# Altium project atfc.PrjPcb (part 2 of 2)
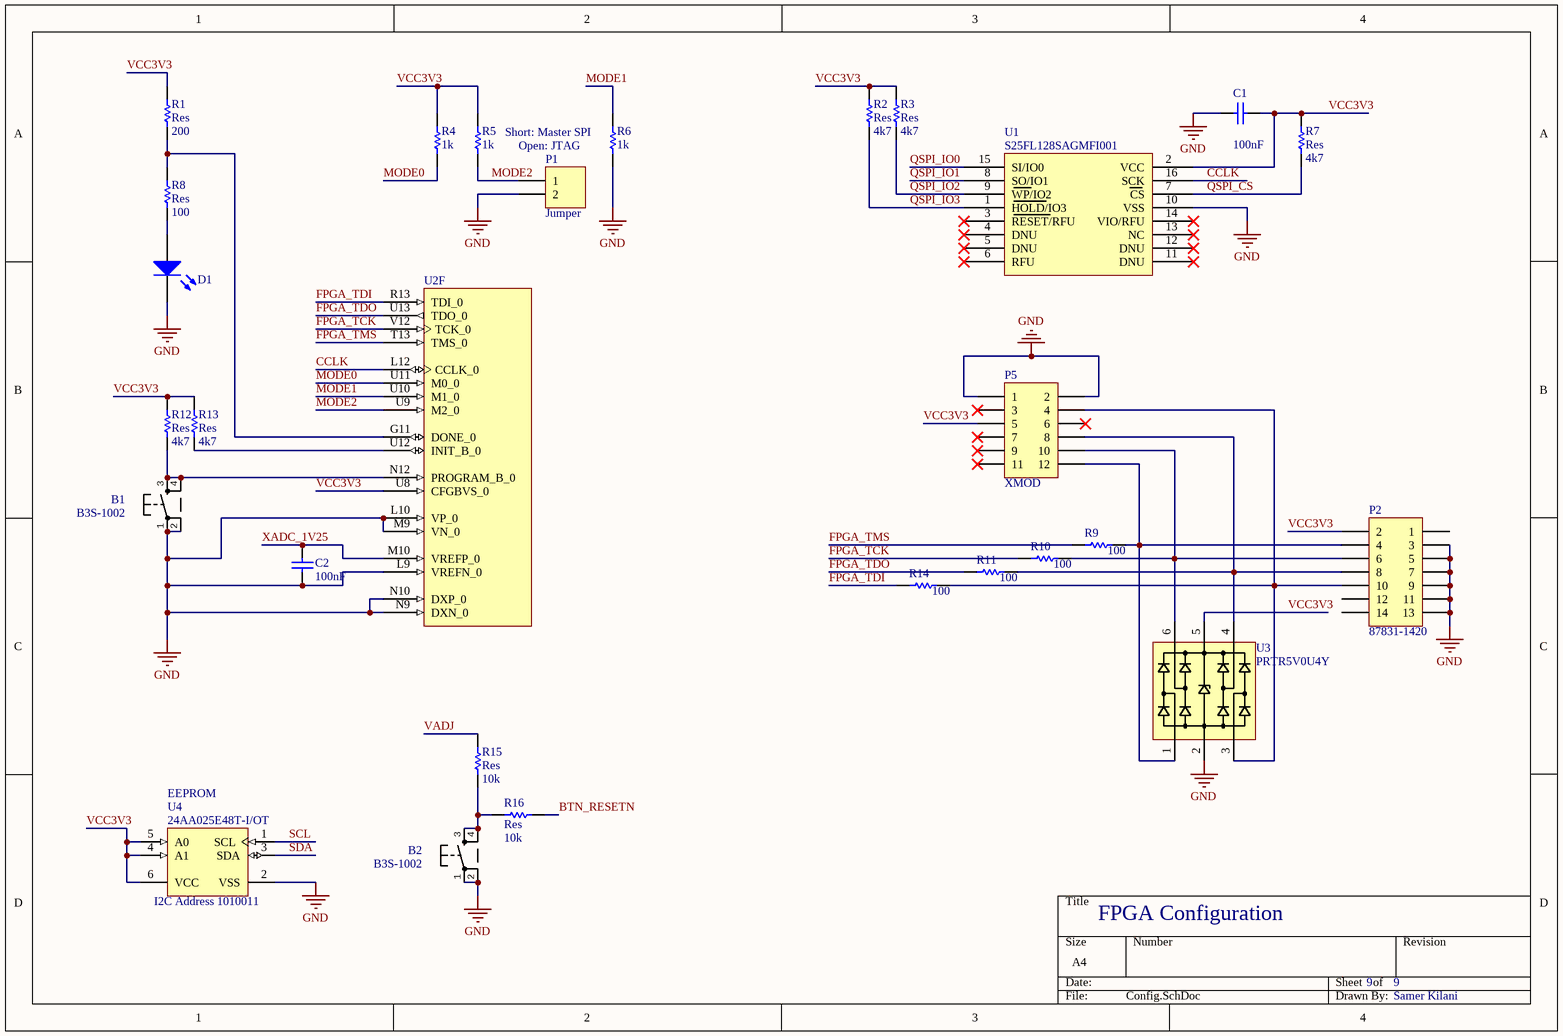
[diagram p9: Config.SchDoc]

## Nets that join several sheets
GND: PWR_APD5052 (51 pins), FPGA_PWR (144 pins), SFP (43 pins), IO (16 pins), FMC (64 pins), FPGA_Banks1 (6 pins), FPGA_Banks2 (6 pins), Regulators (39 pins), Config (25 pins)
3V3_I_MON: PWR_APD5052 (Rout2.2 U10.1), FPGA_Banks1 (U2.H14)
12V0_I_MON: PWR_APD5052 (Rout1.2 U9.1), FPGA_Banks1 (U2.H15)
BTN_RESETN: FPGA_Banks2 (U2.Y2), Config (R16.1)
DIP1: IO (R48.1 S1.1), FPGA_Banks1 (U2.AA18)
DIP2: IO (R49.1 S1.2), FPGA_Banks1 (U2.AA19)
DIP3: IO (R50.1 S1.3), FPGA_Banks1 (U2.AA20)
DIP4: IO (R51.1 S1.4), FPGA_Banks1 (U2.AA21)
FMC_CLK0_M2C_N: FMC (J1.H5), FPGA_Banks2 (U2.W4)
FMC_CLK0_M2C_P: FMC (J1.H4), FPGA_Banks2 (U2.V4)
FMC_CLK1_M2C_N: FMC (J1.G3), FPGA_Banks2 (U2.T4)
FMC_CLK1_M2C_P: FMC (J1.G2), FPGA_Banks2 (U2.R4)
FMC_LA00_CC_N: FMC (J1.G7), FPGA_Banks2 (U2.U5)
FMC_LA00_CC_P: FMC (J1.G6), FPGA_Banks2 (U2.T5)
FMC_LA01_CC_N: FMC (J1.D9), FPGA_Banks2 (U2.AA4)
FMC_LA01_CC_P: FMC (J1.D8), FPGA_Banks2 (U2.Y4)
FMC_LA02_N: FMC (J1.H8), FPGA_Banks2 (U2.K3)
FMC_LA02_P: FMC (J1.H7), FPGA_Banks2 (U2.L3)
FMC_LA03_N: FMC (J1.G10), FPGA_Banks2 (U2.G2)
FMC_LA03_P: FMC (J1.G9), FPGA_Banks2 (U2.H2)
FMC_LA04_N: FMC (J1.H11), FPGA_Banks2 (U2.AB1)
FMC_LA04_P: FMC (J1.H10), FPGA_Banks2 (U2.AA1)
FMC_LA05_N: FMC (J1.D12), FPGA_Banks2 (U2.M2)
FMC_LA05_P: FMC (J1.D11), FPGA_Banks2 (U2.M3)
FMC_LA06_N: FMC (J1.C11), FPGA_Banks2 (U2.AB2)
FMC_LA06_P: FMC (J1.C10), FPGA_Banks2 (U2.AB3)
FMC_LA07_N: FMC (J1.H14), FPGA_Banks2 (U2.Y1)
FMC_LA07_P: FMC (J1.H13), FPGA_Banks2 (U2.W1)
FMC_LA08_N: FMC (J1.G13), FPGA_Banks2 (U2.J2)
FMC_LA08_P: FMC (J1.G12), FPGA_Banks2 (U2.K2)
FMC_LA09_N: FMC (J1.D15), FPGA_Banks2 (U2.R2)
FMC_LA09_P: FMC (J1.D14), FPGA_Banks2 (U2.R3)
FMC_LA10_N: FMC (J1.C15), FPGA_Banks2 (U2.AB5)
FMC_LA10_P: FMC (J1.C14), FPGA_Banks2 (U2.AA5)
FMC_LA11_N: FMC (J1.H17), FPGA_Banks2 (U2.U1)
FMC_LA11_P: FMC (J1.H16), FPGA_Banks2 (U2.T1)
FMC_LA12_N: FMC (J1.G16), FPGA_Banks2 (U2.N3)
FMC_LA12_P: FMC (J1.G15), FPGA_Banks2 (U2.N4)
FMC_LA13_N: FMC (J1.D18), FPGA_Banks2 (U2.AA3)
FMC_LA13_P: FMC (J1.D17), FPGA_Banks2 (U2.Y3)
FMC_LA14_N: FMC (J1.C19), FPGA_Banks2 (U2.AB6)
FMC_LA14_P: FMC (J1.C18), FPGA_Banks2 (U2.AB7)
FMC_LA15_N: FMC (J1.H20), FPGA_Banks2 (U2.P1)
FMC_LA15_P: FMC (J1.H19), FPGA_Banks2 (U2.R1)
FMC_LA16_N: FMC (J1.G19), FPGA_Banks2 (U2.V2)
FMC_LA16_P: FMC (J1.G18), FPGA_Banks2 (U2.U2)
FMC_LA17_CC_N: FMC (J1.D21), FPGA_Banks2 (U2.G4)
FMC_LA17_CC_P: FMC (J1.D20), FPGA_Banks2 (U2.H4)
FMC_LA18_CC_N: FMC (J1.C23), FPGA_Banks2 (U2.J4)
FMC_LA18_CC_P: FMC (J1.C22), FPGA_Banks2 (U2.K4)
FMC_LA19_N: FMC (J1.H23), FPGA_Banks2 (U2.L1)
FMC_LA19_P: FMC (J1.H22), FPGA_Banks2 (U2.M1)
FMC_LA20_N: FMC (J1.G22), FPGA_Banks2 (U2.W5)
FMC_LA20_P: FMC (J1.G21), FPGA_Banks2 (U2.W6)
FMC_LA21_N: FMC (J1.H26), FPGA_Banks2 (U2.J1)
FMC_LA21_P: FMC (J1.H25), FPGA_Banks2 (U2.K1)
FMC_LA22_N: FMC (J1.G25), FPGA_Banks2 (U2.AA6)
FMC_LA22_P: FMC (J1.G24), FPGA_Banks2 (U2.Y6)
FMC_LA23_N: FMC (J1.D24), FPGA_Banks2 (U2.V5)
FMC_LA23_P: FMC (J1.D23), FPGA_Banks2 (U2.U6)
FMC_LA24_N: FMC (J1.H29), FPGA_Banks2 (U2.F1)
FMC_LA24_P: FMC (J1.H28), FPGA_Banks2 (U2.G1)
FMC_LA25_N: FMC (J1.G28), FPGA_Banks2 (U2.Y9)
FMC_LA25_P: FMC (J1.G27), FPGA_Banks2 (U2.W9)
FMC_LA26_N: FMC (J1.D27), FPGA_Banks2 (U2.W7)
FMC_LA26_P: FMC (J1.D26), FPGA_Banks2 (U2.V7)
FMC_LA27_N: FMC (J1.C27), FPGA_Banks2 (U2.AB8)
FMC_LA27_P: FMC (J1.C26), FPGA_Banks2 (U2.AA8)
FMC_LA28_N: FMC (J1.H32), FPGA_Banks2 (U2.B2)
FMC_LA28_P: FMC (J1.H31), FPGA_Banks2 (U2.C2)
FMC_LA29_N: FMC (J1.G31), FPGA_Banks2 (U2.V8)
FMC_LA29_P: FMC (J1.G30), FPGA_Banks2 (U2.V9)
FMC_LA30_N: FMC (J1.H35), FPGA_Banks2 (U2.D1)
FMC_LA30_P: FMC (J1.H34), FPGA_Banks2 (U2.E1)
FMC_LA31_N: FMC (J1.G34), FPGA_Banks2 (U2.L4)
FMC_LA31_P: FMC (J1.G33), FPGA_Banks2 (U2.L5)
FMC_LA32_N: FMC (J1.H38), FPGA_Banks2 (U2.A1)
FMC_LA32_P: FMC (J1.H37), FPGA_Banks2 (U2.B1)
FMC_LA33_N: FMC (J1.G37), FPGA_Banks2 (U2.T6)
FMC_LA33_P: FMC (J1.G36), FPGA_Banks2 (U2.R6)
FMC_MGT_C2M_N: FMC (J1.C3), FPGA_Banks2 (U2.C7)
FMC_MGT_C2M_P: FMC (J1.C2), FPGA_Banks2 (U2.D7)
FMC_MGT_CLK_N: FMC (C4.2), FPGA_Banks2 (U2.E10)
FMC_MGT_CLK_P: FMC (C3.2), FPGA_Banks2 (U2.F10)
FMC_MGT_M2C_N: FMC (J1.C7), FPGA_Banks2 (U2.C9)
FMC_MGT_M2C_P: FMC (J1.C6), FPGA_Banks2 (U2.D9)
FZ1: FPGA_PWR (5 pins), FPGA_Banks2 (35 pins)
LED0: IO (R42.2), FPGA_Banks1 (U2.F21)
LED1: IO (R43.2), FPGA_Banks1 (U2.F20)
MGTAVCC1V0: FPGA_PWR (8 pins), FPGA_Banks1 (R33.2), Regulators (7 pins)
MGTAVTT1V2: FPGA_PWR (9 pins), FPGA_Banks1 (R31.2), FPGA_Banks2 (R37.1), Regulators (C98.1 R77.2 U11.5)
PGOOD: PWR_APD5052 (R75.1 U8.20), IO (Q1.5), FPGA_Banks1 (R21.2)
PGOOD_VADJ: IO (Q1.2), FMC (J1.D1 R17.1), FPGA_Banks1 (R22.2), Regulators (U13.21)
PMODA1_N: IO (R98.1), FPGA_Banks1 (U2.D22)
PMODA1_P: IO (R80.1), FPGA_Banks1 (U2.E22)
PMODA2_N: IO (R102.1), FPGA_Banks1 (U2.H22)
PMODA2_P: IO (R100.1), FPGA_Banks1 (U2.J22)
PMODA3_N: IO (R99.2), FPGA_Banks1 (U2.B22)
PMODA3_P: IO (R97.2), FPGA_Banks1 (U2.C22)
PMODA4_N: IO (R103.2), FPGA_Banks1 (U2.G22)
PMODA4_P: IO (R101.2), FPGA_Banks1 (U2.G21)
PMODB1_N: IO (R106.1), FPGA_Banks1 (U2.C20)
PMODB1_P: IO (R104.1), FPGA_Banks1 (U2.D20)
PMODB2_N: IO (R110.1), FPGA_Banks1 (U2.E14)
PMODB2_P: IO (R108.1), FPGA_Banks1 (U2.E13)
PMODB3_N: IO (R107.2), FPGA_Banks1 (U2.D15)
PMODB3_P: IO (R105.2), FPGA_Banks1 (U2.D14)
PMODB4_N: IO (R111.2), FPGA_Banks1 (U2.D16)
PMODB4_P: IO (R109.2), FPGA_Banks1 (U2.E16)
PRESNT_M2C_L: FMC (J1.H2 R18.1), FPGA_Banks1 (R96.1)
QSPI_CS: FPGA_Banks1 (U2.T19), Config (R7.1 U1.7)
QSPI_IO0: FPGA_Banks1 (U2.P22), Config (U1.15)
QSPI_IO1: FPGA_Banks1 (U2.R22), Config (U1.8)
QSPI_IO2: FPGA_Banks1 (U2.P21), Config (R3.1 U1.9)
QSPI_IO3: FPGA_Banks1 (U2.R21), Config (R2.1 U1.1)
RGB_B1: IO (R38.2), FPGA_Banks1 (U2.C13)
RGB_B2: IO (R40.2), FPGA_Banks1 (U2.C17)
RGB_G1: IO (R39.2), FPGA_Banks1 (U2.C14)
RGB_G2: IO (R41.2), FPGA_Banks1 (U2.C18)
RGB_R1: IO (R44.1), FPGA_Banks1 (U2.C15)
RGB_R2: IO (R45.1), FPGA_Banks1 (U2.C19)
SCL: FMC (J1.C30), FPGA_Banks1 (R35.2 U2.AB21), Config (U4.1)
SDA: FMC (J1.C31), FPGA_Banks1 (R36.2 U2.AB22), Config (U4.3)
SFP1_LOS: SFP (J3.8 R84.2), FPGA_Banks1 (U2.B17)
SFP1_MOD_ABS: SFP (J3.6 R87.2), FPGA_Banks1 (U2.A13)
SFP1_RD_N: SFP (J4.12), FPGA_Banks2 (U2.A8)
SFP1_RD_P: SFP (J4.13), FPGA_Banks2 (U2.B8)
SFP1_SCL: SFP (J3.5 R88.2), FPGA_Banks1 (U2.A16)
SFP1_SDA: SFP (J3.4 R89.2), FPGA_Banks1 (U2.B15)
SFP1_TD_N: SFP (J4.19), FPGA_Banks2 (U2.A4)
SFP1_TD_P: SFP (J4.18), FPGA_Banks2 (U2.B4)
SFP1_TX_EN: SFP (J3.3 R86.2), FPGA_Banks1 (U2.A14)
SFP1_TX_FAULT: SFP (J3.2 R85.2), FPGA_Banks1 (U2.A15)
SFP2_LOS: SFP (J4.8 R90.2), FPGA_Banks1 (U2.B21)
SFP2_MOD_ABS: SFP (J4.6 R93.2), FPGA_Banks1 (U2.A18)
SFP2_RD_N: SFP (J3.12), FPGA_Banks2 (U2.A10)
SFP2_RD_P: SFP (J3.13), FPGA_Banks2 (U2.B10)
SFP2_SCL: SFP (J4.5 R94.2), FPGA_Banks1 (U2.A21)
SFP2_SDA: SFP (J4.4 R95.2), FPGA_Banks1 (U2.B20)
SFP2_TD_N: SFP (J3.19), FPGA_Banks2 (U2.A6)
SFP2_TD_P: SFP (J3.18), FPGA_Banks2 (U2.B6)
SFP2_TX_EN: SFP (J4.3 R92.2), FPGA_Banks1 (U2.A19)
SFP2_TX_FAULT: SFP (J4.2 R91.2), FPGA_Banks1 (U2.A20)
SYSCLK: FPGA_Banks1 (U2.D17), FPGA_Banks2 (IC1.4)
VADJ: FPGA_PWR (25 pins), FMC (J1.G39 J1.H40), FPGA_Banks1 (R25.2), Regulators (R79.2), Config (R15.2)
VADJ_I_MON: FPGA_Banks1 (U2.J15), Regulators (Rout3.2 U12.1)
VCC1V0: PWR_APD5052 (5 pins), FPGA_PWR (25 pins), FPGA_Banks1 (R29.2)
VCC1V8: PWR_APD5052 (5 pins), FPGA_PWR (13 pins), FPGA_Banks1 (R27.2)
VCC2V5: PWR_APD5052 (C95.2 R72.2 U8.7), Regulators (Ren1.1)
VCC3V3: PWR_APD5052 (C76.2 R62.2 U8.8), FPGA_PWR (39 pins), SFP (20 pins), IO (16 pins), FMC (8 pins), FPGA_Banks1 (R23.2 R35.1 R36.1), FPGA_Banks2 (6 pins), Regulators (17 pins), Config (17 pins)
VCC12V0: PWR_APD5052 (14 pins), FMC (J1.C35 J1.C37), Regulators (7 pins)
VREF_A_M2C: FMC (J1.H1), FPGA_Banks2 (U2.E3)
XADC_1V8: FPGA_PWR (C49.2 U2.K10), Regulators (C113.1 R81.2 U15.5)
XADC_1V25: Regulators (C116.1 C117.1 U16.4), Config (C2.2 U2.M10)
